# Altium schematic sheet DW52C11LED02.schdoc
size 127 x 101 mm
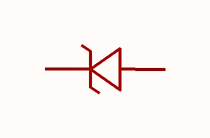
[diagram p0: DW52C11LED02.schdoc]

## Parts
D?  dw52c11led02  [WBFBP-02C]  (value not drawn)

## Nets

Not connected (* = marked no-connect by the designer): D? 1(C) 2(A)

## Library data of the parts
D? = dw52c11led02: 二极管配置:1个独立式;稳压值(标称值):11V;稳压值(范围):10.4V~11.6V;耗散功率(Pd):100mW;; Manufacturer: CJ(江苏长电/长晶); AddInBom: yes; ModelId: 2908ee36a0fc45e8960f4d031d97b95b; ModelTransform: 39.7637,23.622,0,0,0,0,0,0,0; Diode Configuration: 1个独立式; Zener Voltage(Nom): 11V; Reverse Leakage Current (Ir): 100nA; Pd - Power Dissipation: 100mW; Impedance(Zzt): 20Ω; Impedance(Zzk): 150Ω; Operating Junction Temperature Range: -55℃~+150℃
